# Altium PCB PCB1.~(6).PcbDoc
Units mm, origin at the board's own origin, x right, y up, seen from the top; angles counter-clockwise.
Board outline 152.4 x 101.6 mm, 2 copper layers (Top Layer, Bottom Layer); 19 components, 17 nets, 64 pads, 2 vias.
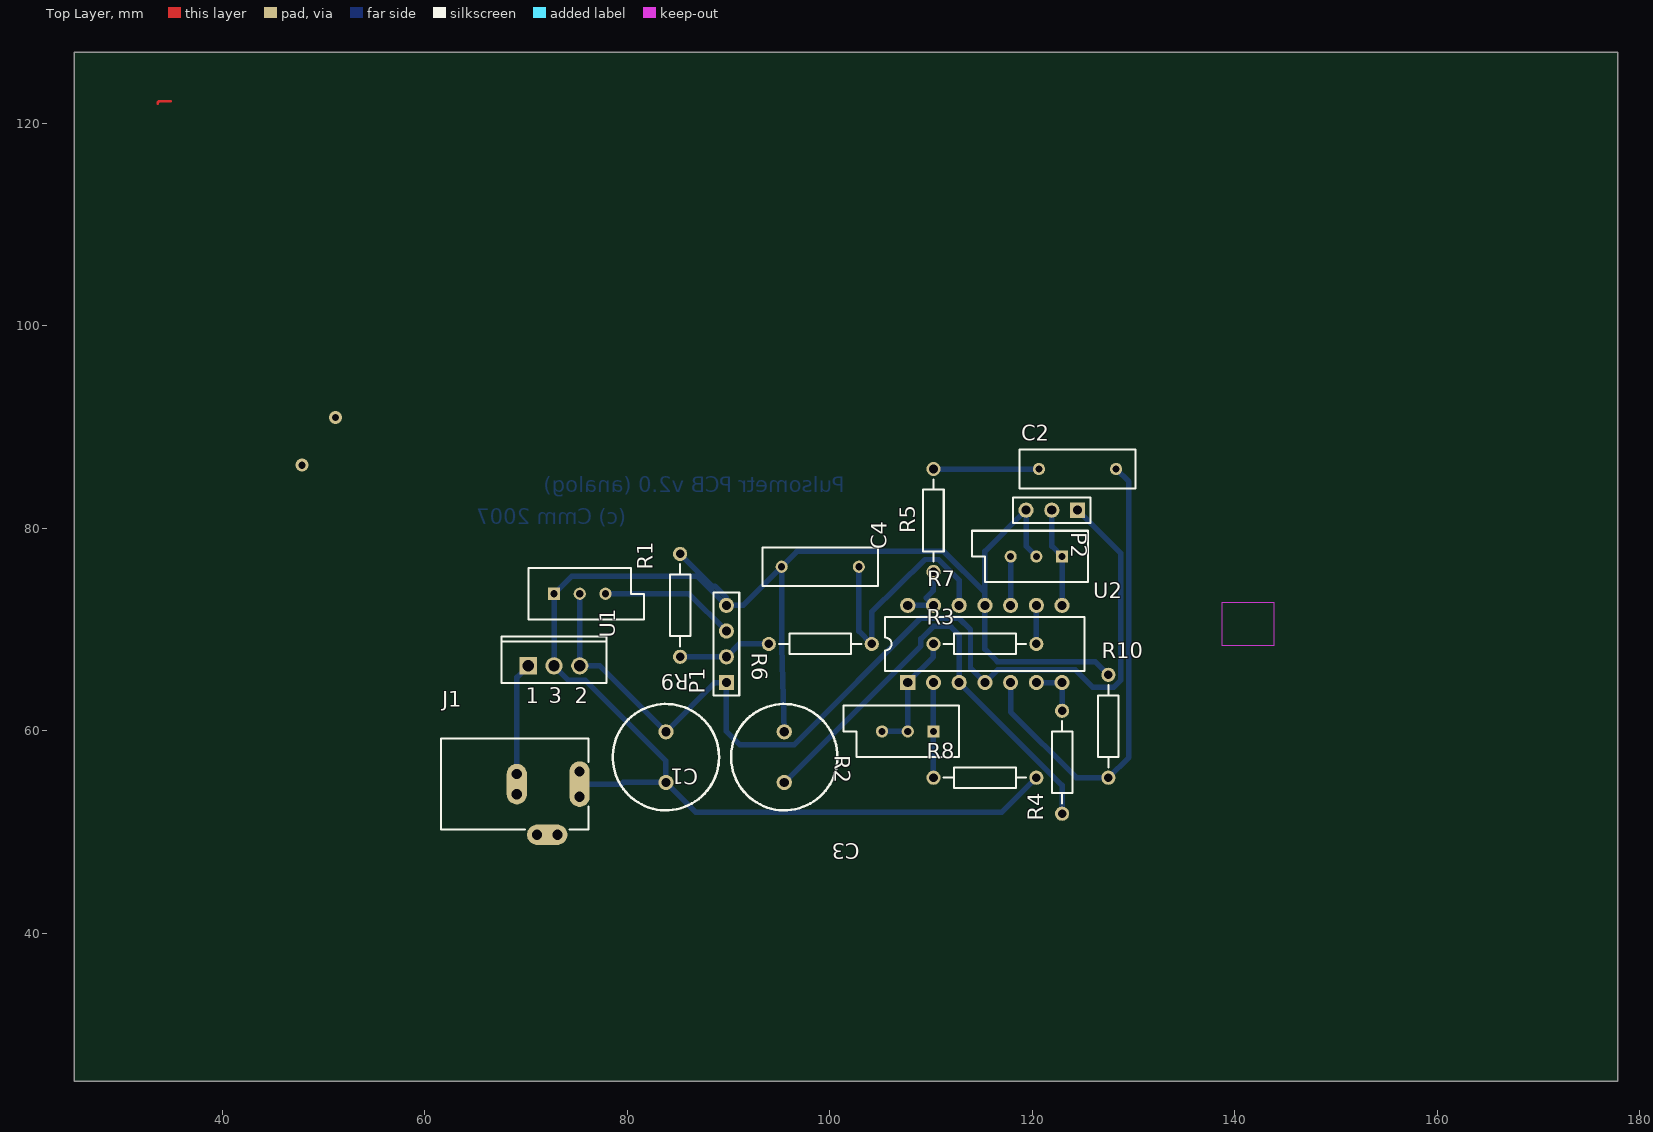
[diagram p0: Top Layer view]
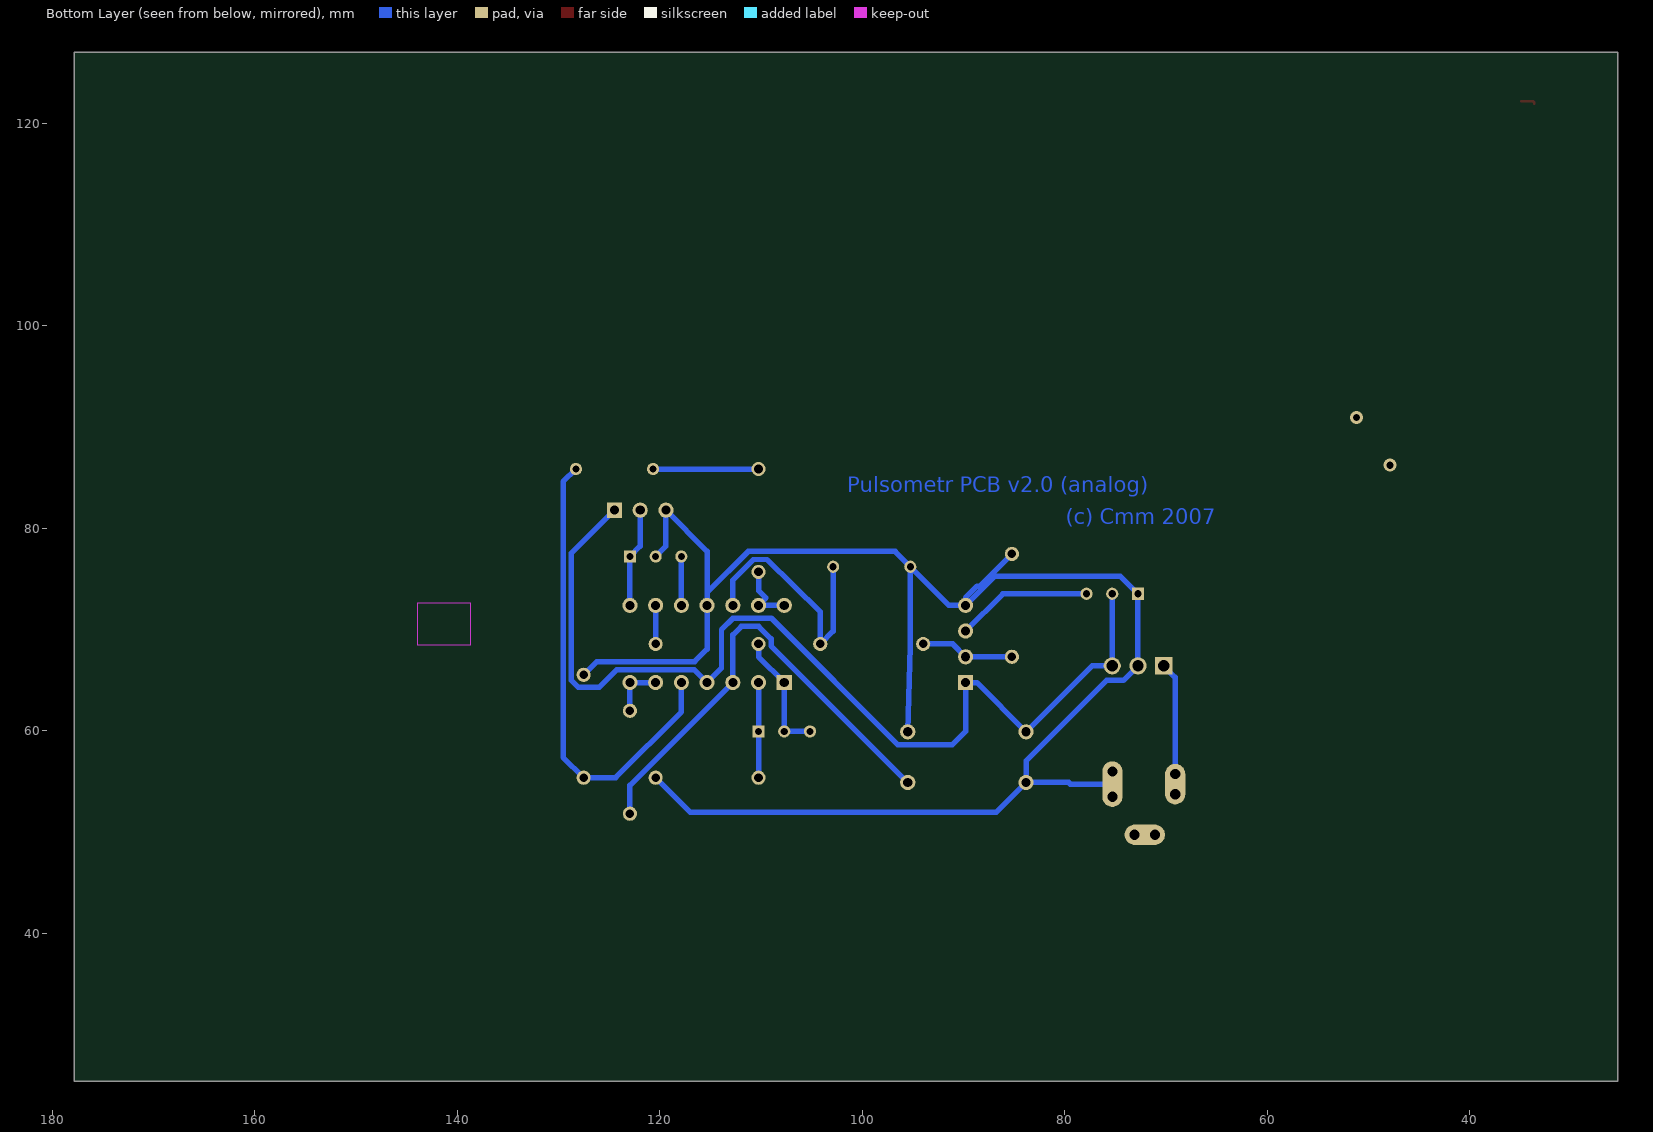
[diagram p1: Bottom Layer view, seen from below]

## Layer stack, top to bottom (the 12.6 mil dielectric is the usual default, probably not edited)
Top Layer: signal copper 0.0356
Dielectric: dielectric 0.32, FR-4, Dk 4.8
Bottom Layer: signal copper 0.0356

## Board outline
25.4,25.4 177.8,25.4 177.8,127 25.4,127

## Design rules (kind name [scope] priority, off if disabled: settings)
Clearance [All] p1: gap=0.254
ComponentClearance [All] p1: gap=0.254 collisioncheckmode=3 verticalgap=0.254
PolygonConnect [All] p1: connectstyle=Relief reliefconductorwidth=0.254 reliefentries=4 polygonreliefangle="90 Angle"
RoomDefinition Sheet1 [InComponentClass('Sheet1')] p1: confinementstyle=ConfineIn formatcopy=TRUE lockcomponents=FALSE outline 59.69,46.863 133.731,46.863 133.731,88.9 59.69,88.9
RoutingVias [All] p1: holewidth=0.711 width=2 viastyle="Through Hole" minholewidth=0.711 minwidth=1.27 maxholewidth=0.711 maxwidth=2.27
SolderMaskExpansion [All] p1: expansion=0.102
TestPointUsage [All] p1: valid=0 allowmultiple=FALSE
Testpoint [All] p1: side=15 testpointundercomponent=TRUE minsize=1.016 maxsize=2.54 preferedsize=1.524 minholesize=0 maxholesize=1.016 preferedholesize=0.813 testpointgrid=0.025 style=1023 order=0123456789
Width [All] p1: maxlimit=1254 minlimit=0.254 preferedwidth=0.254 toplayer_maxwidth=1.254 toplayer_prefwidth=0.54 bottomlayer_prefwidth=0.54 minimp=50.000000 maximp=50.000000 favimp=50.000000
18 further rules are at their usual default settings.

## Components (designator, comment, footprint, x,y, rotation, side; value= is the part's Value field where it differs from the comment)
C1 "Cap Pol1" RB5-10.5 83.82,57.404 r90 top
C2 "Cap" RAD-0.3 124.46,85.852 r180 top
C3 "Cap Pol1" RB5-10.5 95.504,57.404 r90 top
C4 "Cap" RAD-0.3 99.06,76.2 r0 top
J1 "PWR2.5" KLD-0202 61.595,54.737 r0 top
P1 "Header 4" HDR1X4 89.789,64.77 r90 top
P2 "Header 3" HDR1X3 124.46,81.788 r180 top
R1 "RPot" VR5 75.311,73.533 r0 top
R2 "RPot" VR5 107.696,59.944 r180 top
R3 "Res2" AXIAL-0.4 115.316,68.58 r180 top
R4 "Res2" AXIAL-0.4 122.936,56.896 r90 top
R5 "Res2" AXIAL-0.4 110.236,80.772 r270 top
R6 "Res2" AXIAL-0.4 99.06,68.58 r180 top
R7 "RPot" VR5 120.396,77.216 r180 top
R8 "Res2" AXIAL-0.4 115.316,55.372 r0 top
R9 "Res2" AXIAL-0.4 85.217,72.39 r270 top
R10 "Res2" AXIAL-0.4 127.508,60.452 r90 top
U1 "L7812ABV" TO220ABN 72.771,66.421 r0 top
U2 "LM324AN" N14A 115.316,68.58 r0 top

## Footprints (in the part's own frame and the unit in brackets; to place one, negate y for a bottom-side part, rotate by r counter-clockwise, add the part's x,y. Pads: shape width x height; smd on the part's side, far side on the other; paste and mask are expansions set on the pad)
AXIAL-0.4 [mm] "Resistor; 2 Leads"
  round 1.4 hole 0.85: 1(-5.08,0) 2(5.08,0)
  silkscreen extent -4.06,-1.02 4.06,1.02
HDR1X3 [mm] "Connector; Header; 3 Position"
  rect 1.5x1.5 hole 0.9: 1(0,0)
  round 1.5 hole 0.9: 2(2.54,0) 3(5.08,0)
  silkscreen extent -1.27,-1.27 6.35,1.27
HDR1X4 [mm] "Connector; Header; 4 Position"
  rect 1.5x1.5 hole 0.9: 1(0,0)
  round 1.5 hole 0.9: 2(2.54,0) 3(5.08,0) 4(7.62,0)
  silkscreen extent -1.27,-1.27 8.89,1.27
KLD-0202 [mm] "DC Power Jack, 2.5mm, KLD Series, PCB Mount"
  oval 2x4.5 all layers, no hole: 1(13.7,0)
  round 1.5 hole 1: 1A(13.7,-1.25) 1B(13.7,1.25) 2A(7.5,-1) 2B(7.5,1) 3A(9.5,-5) 3B(11.5,-5)
  oval 2x4 all layers, no hole: 2(7.5,0)
  oval 4x2 all layers, no hole: 3(10.5,-5)
  silkscreen extent 0,-4.5 14.6,4.5
N14A [mm] "DIP; 14 Leads; Row Spacing 7.62 mm; Pitch 2.54 mm"
  rect 1.5x1.5 hole 0.9: 1(-7.62,-3.81)
  round 1.5 hole 0.9: 2(-5.08,-3.81) 3(-2.54,-3.81) 4(0,-3.81) 5(2.54,-3.81) 6(5.08,-3.81) 7(7.62,-3.81) 8(7.62,3.81) 9(5.08,3.81) 10(2.54,3.81) 11(0,3.81) 12(-2.54,3.81) 13(-5.08,3.81) 14(-7.62,3.81)
  silkscreen extent -9.85,-2.65 9.85,2.65
RAD-0.3 [mm] "Capacitor; 2 Leads"
  round 1.2 hole 0.7: 1(-3.81,0) 2(3.81,0)
  silkscreen extent -5.71,-1.91 5.71,1.91
RB5-10.5 [mm] "Motor, General Kind; 2 Leads"
  round 1.5 hole 0.9: 1(-2.5,0) 2(2.5,0)
  silkscreen extent -5.25,-5.25 5.25,5.25
TO220ABN [mm] "TO, Thru-Hole, Vertical, Heatsink Mounted; 3 In-Line Leads; Pitch 2.54 mm; Pin sequence 1, 3, 2"
  rect 1.7x1.7 hole 1.1: 1(-2.54,0)
  round 1.7 hole 1.1: 2(2.54,0) 3(0,0)
  silkscreen extent -5.2,-1.7 5.2,2.9
VR5 [mm] "Potentiometer; 3 Leads"
  rect 1.2x1.2 hole 0.7: 1(-2.54,0)
  round 1.2 hole 0.7: 2(0,0) 3(2.54,0)
  silkscreen extent -5.08,-2.54 6.35,2.54

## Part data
C1 C3: "Polarized Capacitor (Radial)"
C2 C4: "Capacitor"
J1: "Low Voltage Power Supply Connector"
P1: "Header, 4-Pin"
P2: library part "Header 2", "Header, 2-Pin"
R1 R2 R7: "Potentiometer"
R3 R4 R5 R6 R8 R9 R10: "Resistor"
U1: "Precision 1A Regulator"
U2: "Low-Power Quad Operational Amplifier"

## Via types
v1: diameter 1.27, hole 0.711, Top Layer to Bottom Layer, 2 vias

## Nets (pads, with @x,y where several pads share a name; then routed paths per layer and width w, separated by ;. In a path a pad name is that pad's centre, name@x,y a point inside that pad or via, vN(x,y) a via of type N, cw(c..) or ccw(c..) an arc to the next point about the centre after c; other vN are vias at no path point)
+5: C1.2 P1.1 P2.1 R1.2 U1.2 U2.4 | length 100.8
  Bottom Layer w0.54: R1.2 U1.2 77.303,66.421 C1.2 88.686,64.77 P1.1 89.789,59.944 91.11,58.623 96.473,58.623 108.966,71.116 112.776,71.116 113.894,69.998 113.894,66.192 U2.4 116.59,66.044 124.227,66.044 125.984,64.287 128.016,64.287 128.732,65.003 128.732,77.516 P2.1
GND: C1.1 C3.2 C4.1 J1.1 J1.1A J1.1B P1.4 P2.3 R1.1 R7.2 R8.2 R9.1 R10.2 U1.3 U2.11 | length 179.9
  Bottom Layer w0.54: J1.1A J1.1 ; J1.1B J1.1 ; R9.1 88.392,74.295 88.646,74.295 89.789,73.152 P1.4 ; C3.2 95.25,68.326 C4.1 ; R8.2 116.992,51.968 86.756,51.968 C1.1 ; R7.2 119.38,78.232 P2.3 115.316,77.724 115.316,73.646 ; R10.2 126.202,66.838 116.55,66.838 115.316,68.072 U2.11 115.316,73.646 ; J1.1 79.451,54.737 79.618,54.904 C1.1 ; C1.1 83.82,57.023 75.87,64.973 74.219,64.973 U1.3 R1.1 74.498,75.26 86.919,75.26 P1.4 ; P1.4 91.44,72.39 C4.1 ; C4.1 96.76,77.71 111.252,77.71 115.316,73.646
NetC2_1: C2.1 R10.1 U2.5 | length 47.1
  Bottom Layer w0.54: U2.5 117.856,61.874 124.358,55.372 R10.1 129.526,57.39 129.526,84.596 C2.1
NetC2_2: C2.2 R5.1 | length 10.4
  Bottom Layer w0.54: R5.1 C2.2
NetC3_1: C3.1 R4.1 U2.3 | length 46.3
  Bottom Layer w0.54: C3.1 108.991,68.391 108.991,69.088 110.225,70.322 111.923,70.322 112.776,69.469 U2.3 122.936,54.61 R4.1
NetC4_2: C4.2 R6.1 U2.12 | length 25.4
  Bottom Layer w0.54: C4.2 102.87,69.85 R6.1 104.14,71.755 109.403,76.916 110.744,76.916 112.776,74.884 U2.12
NetJ1_3: J1.3 J1.3A J1.3B | length 2
  Bottom Layer w0.54: J1.3A J1.3 J1.3B
NetP1_2: P1.2 R6.2 R9.2 | length 9.3
  Bottom Layer w0.54: R9.2 P1.2 91.059,68.58 R6.2
NetP1_3: P1.3 R1.3 | length 13.5
  Bottom Layer w0.54: R1.3 86.106,73.533 P1.3
NetP2_2: P2.2 R7.1 U2.8 | length 9.8
  Bottom Layer w0.54: P2.2 121.92,78.232 R7.1 U2.8
NetR2_1: R2.1 R8.1 U2.2 | length 9.4
  Bottom Layer w0.54: R8.1 R2.1 U2.2
NetR2_2: R2.2 R2.3 R3.2 U2.1 | length 12.2
  Bottom Layer w0.54: R2.3 R2.2 U2.1 110.236,67.31 R3.2
NetR3_1: R3.1 U2.9 | length 3.8
  Bottom Layer w0.54: R3.1 U2.9
NetR4_2: R4.2 U2.6 U2.7 | length 5.4
  Bottom Layer w0.54: U2.6 120.426,64.74 122.906,64.74 U2.7 R4.2
NetR5_2: R5.2 U2.13 U2.14 | length 6.4
  Bottom Layer w0.54: U2.14 U2.13 109.505,73.121 110.236,73.851 R5.2
NetR7_3: R7.3 U2.10 | length 4.8
  Bottom Layer w0.54: U2.10 R7.3
VCC: J1.2 J1.2A J1.2B U1.1 | length 13.2
  Bottom Layer w0.54: J1.2A J1.2 J1.2B 69.095,65.285 U1.1
copper on no net: | length 1.4
  Top Layer w0.254: 33.655,121.92 33.655,122.047 33.782,122.174 34.925,122.174
  other v1: 47.879,86.233 51.181,90.932

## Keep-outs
Keep-Out Layer:
  rectangle: 138.684,68.453 143.891,72.644

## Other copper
Bottom Layer:
  text "Pulsometr PCB v2.0 (analog)" at 101.473,83.566 h1.52
  text "(c) Cmm 2007" at 79.883,80.391 h1.52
